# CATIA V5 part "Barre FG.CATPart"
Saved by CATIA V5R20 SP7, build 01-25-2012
Part number: Barre FG modifiée
Bounding box of the stored display mesh (mm): x -3 to 3, y -19.215 to 15.78, z 15.685 to 43.054
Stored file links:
  U:\IAO_bon\Barre FG.CATPart
  U:\IAO_bon\Cqueguiner_IAo.CATProduct
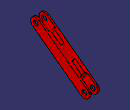
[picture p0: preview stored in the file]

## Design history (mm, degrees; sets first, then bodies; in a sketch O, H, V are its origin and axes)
Set1
  Point1 "Point F": linked copy from another document
  Point2 "Point B/G": linked copy from another document
Set2
  Plane1: type Offset, RefPlane face of Pad1 from Sketch1.L1, Offset -3, reversed
Body1 (main body)
  Sketch1 on yz-plane, origin (0, 0, 0), H (0, 1, 0), V (0, 0, 1)
    line L1 (-14.454, 42.4759) -> (14.5773, 21.0941)
    arc A1 centre (12.7983, 18.6785) radius 3 from (14.5773, 21.0941) to (11.0192, 16.263) cw
    point P3 (12.7983, 18.6785)
    line L2 (11.0192, 16.263) -> (-18.0121, 37.6448)
    arc A2 centre (-16.2331, 40.0604) radius 3 from (-18.0121, 37.6448) to (-14.454, 42.4759) cw
    point P6 (-16.2331, 40.0604)
    reference projected point E1 (-16.2331, 40.0604) from Point1
    reference projected point E2 (12.7983, 18.6785) from Point2
    circle A3 centre (12.7983, 18.6785) radius 1.5
    circle A4 centre (-16.2331, 40.0604) radius 1.5
    distance L2 L1 = 6
    radius A3 = 1.5
    radius A4 = 1.5
    tangency: A1 L1, L2 A1, A2 L1, A2 L2
    coincidence: P6 E1, P3 E2
  Pad1: profile Sketch1, direction (1, 0, 0), length 3, opposite side length 3
  Sketch2 on face of Pad1 from Sketch1.L1, origin (0, 15.1988, 20.6363), H (-1, 0, 0), V (0, -0.8052, 0.593)
    line L1 (-2, 6.7719) -> (2, 6.7719)
    line L2 (2, 6.7719) -> (2, -4.2281)
    line L3 (2, -4.2281) -> (-2, -4.2281)
    line L4 (-2, -4.2281) -> (-2, 6.7719)
    reference projected line E1 through (0, 0.7719) direction (-1, 0) from axis of face of Pad1 from Sketch1.A1
    length L1 = 4
    length L2 = 11
    distance E1 L1 = 6
    horizontal: L1 H, L3 H
    vertical: L2 V, L4 V
  Pocket1: profile Sketch2, direction (0, -0.593, -0.8052), through (limit type 6)
  Sketch3 on face of Pad1 from Sketch1.L1, origin (0, 15.1988, 20.6363), H (-1, 0, 0), V (0, -0.8052, 0.593)
    line L1 (-2, 40.8274) -> (2, 40.8274)
    line L2 (2, 40.8274) -> (2, 30.8274)
    line L3 (2, 30.8274) -> (-2, 30.8274)
    line L4 (-2, 30.8274) -> (-2, 40.8274)
    reference projected line E1 through (0, 36.8274) direction (-1, 0) from axis of face of Pad1 from Sketch1.A2
    length L3 = 4
    length L2 = 10
    distance E1 L3 = 6
    horizontal: L1 H, L3 H
    vertical: L2 V, L4 V
  Pocket2: profile Sketch3, direction (0, -0.593, -0.8052), through (limit type 6)
  Sketch4 on face of Pad1 from Sketch1.L1, origin (0, 15.1988, 20.6363), H (-1, 0, 0), V (0, -0.8052, 0.593)
    line L1 (-1, 34) -> (1, 34)
    line L2 (1, 34) -> (1, 22.8274)
    line L3 (1, 22.8274) -> (-1, 22.8274)
    line L4 (-1, 22.8274) -> (-1, 34)
    point P5 (-1, 14.7719)
    line L5 (-1, 14.7719) -> (1, 14.7719)
    line L6 (1, 14.7719) -> (1, 5)
    line L7 (1, 5) -> (-1, 5)
    line L8 (-1, 5) -> (-1, 14.7719)
    point P7 (1, 5)
    reference projected line E1 through (0, 36.8274) direction (-1, 0) from axis of face of Pad1 from Sketch1.A2
    reference projected line E2 through (0, 0.7719) direction (-1, 0) from axis of face of Pad1 from Sketch1.A1
    distance V L6 = 1
    length L7 = 2
    distance L3 E1 = 14
    distance E2 L5 = 14
    horizontal: L1 H, L3 H, L5 H, L7 H
    vertical: L2 V, L4 V, L6 V, L8 V
    coincidence: P5 L4, P7 L2
  Pocket3: profile Sketch4, direction (0, -0.593, -0.8052), through (limit type 6)
  Chamfer1: length 1, angle 45, on edge [face of Pocket2 from Sketch3.L3 | face of Pocket3 from Sketch4.L2]; edge [face of Pocket3 from Sketch4.L4 | face of Pocket2 from Sketch3.L3]; edge [face of Pocket3 from Sketch4.L6 | face of Pocket1 from Sketch2.L1]; edge [face of Pocket1 from Sketch2.L1 | face of Pocket3 from Sketch4.L8]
